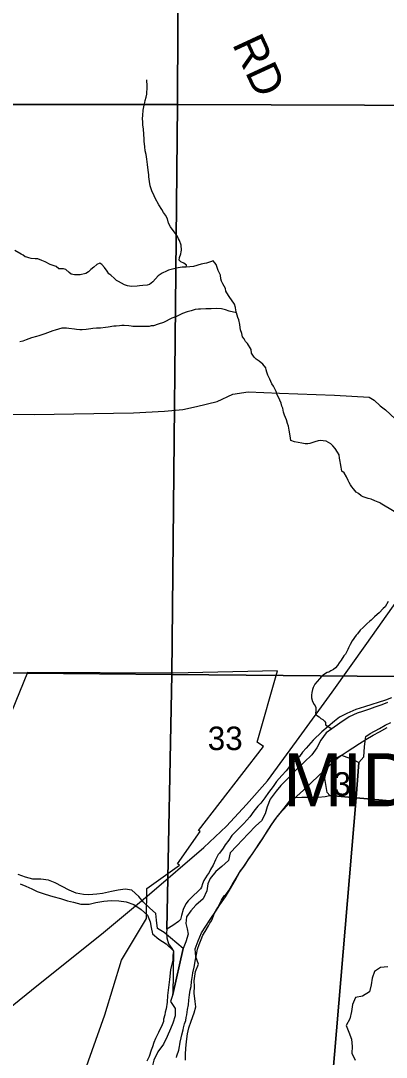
# Model space of a CAD drawing. Extents: x 0 to 34, y 0 to 22.
# Drawn here: x 3.881 to 4.533, y 15.439 to 17.286 of the extents above; entities that cross this region are included whole.
import ezdxf

# ---------------------------------------------------------------- set-up
doc = ezdxf.new("R2010")
doc.units = 0
for name, color, linetype in [('GM_X_Corporation', 7, 'Continuous'), ('GM_X_Corporation_Text', 7, 'Continuous'), ('GM_X_County_Road', 7, 'Continuous'), ('GM_X_Major_River', 7, 'Continuous'), ('GM_X_Minor_Lake', 7, 'Continuous'), ('GM_X_Minor_River', 7, 'Continuous'), ('GM_X_Rail_Line', 7, 'Continuous'), ('GM_X_Section_Text', 7, 'Continuous'), ('GM_X_Township_Road_Text', 7, 'Continuous')]:
    doc.layers.add(name, color=color, linetype=linetype)

msp = doc.modelspace()

# ---------------------------------------------------------------- linework, layer by layer
at = {"layer": 'GM_X_Corporation'}
for points in [[(4.1647, 18.1352), (4.1603, 17.1368), (3.1266, 17.137), (3.1398, 18.1413)], [(4.1647, 18.1352), (5.169, 18.1258), (5.1609, 17.1336), (4.1603, 17.1368)], [(4.1603, 17.1368), (4.1502, 16.1212), (3.1186, 16.1305), (3.1266, 17.137)], [(4.4839, 15.964), (4.4791, 15.9012), (4.4319, 15.9053), (4.4271, 15.9108), (4.423, 15.9356), (4.4289, 15.9641), (4.4529, 15.977), (4.4738, 15.9693)], [(4.4791, 15.9012), (5.4696, 15.8133), (5.3881, 14.7897), (4.6238, 14.8425), (4.6032, 14.8565), (4.5856, 14.8637), (4.5735, 14.8663), (4.5679, 14.8668), (4.5637, 14.865), (4.5556, 14.8606), (4.5464, 14.8574), (4.5354, 14.8542), (4.5274, 14.851), (4.4054, 15.0286)]]:
    msp.add_lwpolyline(points, close=True, dxfattribs=at)
for points in [[(4.6133, 16.1169), (4.1502, 16.1212), (4.1603, 17.1368), (5.1609, 17.1336)], [(3.1186, 16.1305), (4.1502, 16.1212), (4.1415, 15.6672), (4.1406, 15.66), (4.1412, 15.6517), (4.1447, 15.6406), (4.1506, 15.6325), (4.1532, 15.6279), (4.1523, 15.6204), (4.1521, 15.6117), (4.15, 15.6023), (4.1483, 15.5943), (4.1464, 15.577), (4.1424, 15.5486), (4.1418, 15.5369), (4.14, 15.5248), (4.1387, 15.5188), (4.1379, 15.5146), (4.1358, 15.5067), (4.1353, 15.5026), (4.1329, 15.4962), (4.1266, 15.4831), (4.1214, 15.4722), (4.1182, 15.4651), (4.1162, 15.4572), (4.1134, 15.4512), (4.1098, 15.4402), (4.1058, 15.432)], [(3.9341, 15.2418), (4.0311, 15.5141), (4.0604, 15.6115), (4.1055, 15.6858), (4.1057, 15.7394), (4.1642, 15.7809), (4.1606, 15.7834), (4.2008, 15.8408), (4.1977, 15.843), (4.3138, 15.9926), (4.3027, 16.0005), (4.3388, 16.1275), (4.1527, 16.1234), (3.8931, 16.1244), (3.7783, 15.844)], [(4.5417, 16.0791), (4.5314, 16.0751), (4.4936, 16.063), (4.4784, 16.0584), (4.4623, 16.0512), (4.4493, 16.0447), (4.4404, 16.038), (4.4176, 16.0185), (4.4022, 16.0036), (4.3897, 15.9895), (4.3832, 15.9825), (4.3777, 15.975), (4.3722, 15.9683), (4.3653, 15.9624), (4.3599, 15.9568), (4.354, 15.949), (4.3463, 15.9408), (4.337, 15.93), (4.3311, 15.9215), (4.3229, 15.9103), (4.3163, 15.901), (4.3089, 15.8916), (4.3034, 15.8861), (4.2968, 15.8771), (4.2894, 15.8674), (4.2789, 15.8552), (4.2638, 15.8407), (4.2576, 15.834), (4.2521, 15.8258), (4.2455, 15.8176), (4.242, 15.8116), (4.2354, 15.8027), (4.233, 15.8001), (4.2283, 15.7903), (4.2239, 15.7813), (4.2196, 15.7735), (4.2168, 15.7682), (4.2133, 15.763), (4.2074, 15.7537), (4.205, 15.7477), (4.203, 15.742), (4.2014, 15.7386), (4.1968, 15.7342), (4.1883, 15.7264), (4.1797, 15.7175), (4.1754, 15.7119), (4.1707, 15.7022), (4.1678, 15.6916), (4.1658, 15.6845), (4.1623, 15.6808), (4.1523, 15.6738), (4.1415, 15.6672), (4.1502, 16.1212), (4.6133, 16.1169)], [(5.4696, 15.8133), (4.4791, 15.9012), (4.4839, 15.964), (4.4928, 15.9744), (4.494, 15.9922), (4.4954, 16.0066), (4.4963, 16.0103), (4.5039, 16.0155), (4.5204, 16.0246), (4.5308, 16.0308), (4.5407, 16.0355)], [(4.159, 15.4384), (4.1594, 15.4411), (4.163, 15.4512), (4.1643, 15.4576), (4.1648, 15.4614), (4.1652, 15.4656), (4.1673, 15.4731), (4.1685, 15.4788), (4.1706, 15.4874), (4.1711, 15.4912), (4.1727, 15.498), (4.1751, 15.504), (4.176, 15.5097), (4.1769, 15.5146), (4.1786, 15.5236), (4.1799, 15.5323), (4.1809, 15.5406), (4.1818, 15.5501), (4.1831, 15.5584), (4.1848, 15.5651), (4.1857, 15.5735), (4.1875, 15.5844), (4.1879, 15.5889), (4.1901, 15.5991), (4.1926, 15.6131), (4.1943, 15.6221), (4.1961, 15.6312), (4.1989, 15.6395), (4.2025, 15.6485), (4.2057, 15.6564), (4.2096, 15.6631), (4.2155, 15.6728), (4.2183, 15.6777), (4.221, 15.6818), (4.2226, 15.6863), (4.2266, 15.6953), (4.2321, 15.7058), (4.2392, 15.7189), (4.2436, 15.7264), (4.2466, 15.729), (4.2494, 15.7323), (4.2517, 15.7357), (4.2592, 15.7484), (4.2651, 15.7581), (4.2729, 15.7712), (4.2776, 15.7772), (4.2808, 15.7824), (4.289, 15.794), (4.2929, 15.7992), (4.2976, 15.8067), (4.3081, 15.822), (4.312, 15.8283), (4.3187, 15.838), (4.325, 15.8485), (4.3281, 15.853), (4.3375, 15.8664), (4.346, 15.8768), (4.3569, 15.891), (4.3651, 15.9014), (4.3818, 15.9022), (4.411, 15.9023), (4.4235, 15.9032), (4.4319, 15.9053), (4.4791, 15.9012), (4.4054, 15.0286)]]:
    msp.add_lwpolyline(points, dxfattribs=at)
at = {"layer": 'GM_X_County_Road'}
msp.add_lwpolyline([(3.7241, 16.5854), (3.9049, 16.5844), (4.0823, 16.5872), (4.1373, 16.59), (4.1698, 16.5932), (4.1944, 16.5988), (4.2309, 16.6077), (4.2593, 16.6207), (4.2867, 16.6246), (4.3422, 16.6223), (4.4404, 16.619), (4.5023, 16.6152), (4.5112, 16.6097), (4.522, 16.6), (4.5311, 16.5928), (4.5572, 16.5681), (4.5938, 16.5369), (4.6091, 16.5261)], dxfattribs=at)
at = {"layer": 'GM_X_Major_River'}
msp.add_line((4.1705, 15.6327), (4.1523, 15.5504), dxfattribs=at)
for points in [[(4.535, 16.0708), (4.5246, 16.0669), (4.5124, 16.0627), (4.5028, 16.0592), (4.4905, 16.0549), (4.4805, 16.0518), (4.4667, 16.0457), (4.4497, 16.034), (4.4357, 16.0241), (4.4257, 16.0172), (4.4162, 16.0038), (4.409, 15.9903), (4.3999, 15.9777), (4.3862, 15.9644), (4.3734, 15.9522), (4.3593, 15.9381), (4.3448, 15.9233), (4.3362, 15.9129), (4.3256, 15.8988), (4.3206, 15.8853), (4.3169, 15.8728), (4.3101, 15.8601), (4.2999, 15.8509), (4.2863, 15.8372), (4.2761, 15.8265), (4.2663, 15.8153), (4.2542, 15.8031), (4.2512, 15.7896), (4.2395, 15.7789), (4.229, 15.7697), (4.2187, 15.7574), (4.2143, 15.7477), (4.2128, 15.7355), (4.206, 15.7213), (4.1931, 15.7099), (4.1841, 15.6999), (4.1766, 15.6891), (4.1755, 15.6769), (4.1779, 15.6674), (4.1795, 15.6579), (4.1754, 15.6443), (4.1705, 15.6327)], [(4.193, 15.5284), (4.1918, 15.538), (4.1903, 15.5532), (4.191, 15.5657), (4.1902, 15.5752), (4.1925, 15.5915), (4.1978, 15.6046), (4.1929, 15.6176), (4.1917, 15.6317), (4.1974, 15.646), (4.2035, 15.6606), (4.2107, 15.6722), (4.2186, 15.6845), (4.2301, 15.7009), (4.2361, 15.7106), (4.2459, 15.7248), (4.2531, 15.7364), (4.2631, 15.7536), (4.2707, 15.7678), (4.2797, 15.7797), (4.2861, 15.7894), (4.2964, 15.8047), (4.3055, 15.8177), (4.3126, 15.8289), (4.321, 15.8424), (4.3289, 15.8543), (4.336, 15.8643), (4.3462, 15.8774), (4.3583, 15.8896), (4.3732, 15.9043), (4.3849, 15.915), (4.4118, 15.9405), (4.4277, 15.9553), (4.4406, 15.9674), (4.4507, 15.9755), (4.4627, 15.9839), (4.4728, 15.9905), (4.4851, 15.9978), (4.496, 16.0051), (4.5095, 16.0127), (4.5203, 16.0188), (4.5341, 16.0264)], [(4.1523, 15.5504), (4.1481, 15.538), (4.1565, 15.5256), (4.1565, 15.5127), (4.152, 15.4992), (4.1483, 15.4894), (4.1422, 15.4755), (4.1354, 15.462), (4.1255, 15.4482), (4.1183, 15.4333), (4.1145, 15.4193), (4.1127, 15.4091), (4.1103, 15.3928), (4.1077, 15.3815), (4.1052, 15.371), (4.1015, 15.3604), (4.095, 15.3477), (4.0871, 15.3361), (4.0742, 15.3228)], [(4.1745, 15.4333), (4.1748, 15.4443), (4.1754, 15.4541), (4.1765, 15.467), (4.1784, 15.4802), (4.1806, 15.4912), (4.1847, 15.5028), (4.1901, 15.5179), (4.193, 15.5284)]]:
    msp.add_lwpolyline(points, dxfattribs=at)
at = {"layer": 'GM_X_Minor_Lake'}
msp.add_lwpolyline([(4.5356, 15.5997), (4.5223, 15.5985), (4.5115, 15.5916), (4.5077, 15.5796), (4.5059, 15.5675), (4.5025, 15.5554), (4.4905, 15.5478), (4.4775, 15.5451), (4.4723, 15.5327), (4.4704, 15.5202), (4.4674, 15.507), (4.4614, 15.4954), (4.4656, 15.4832), (4.4709, 15.4709), (4.4721, 15.4579), (4.4714, 15.4458), (4.4771, 15.4335)], dxfattribs=at)
at = {"layer": 'GM_X_Minor_River'}
msp.add_line((4.1523, 15.5504), (4.1705, 15.6327), dxfattribs=at)
for points in [[(4.1757, 16.8471), (4.1765, 16.8505), (4.1716, 16.8539), (4.1663, 16.8562), (4.1637, 16.8597), (4.1641, 16.8639), (4.1664, 16.8707), (4.1672, 16.8741), (4.1676, 16.8775), (4.1673, 16.8862), (4.1643, 16.8942), (4.1625, 16.8976), (4.1598, 16.903), (4.1546, 16.9102), (4.1482, 16.919), (4.1445, 16.9255), (4.1427, 16.9331), (4.1393, 16.9395), (4.1356, 16.9441), (4.1326, 16.9498), (4.127, 16.9582), (4.1206, 16.9697), (4.1188, 16.9739), (4.1147, 16.983), (4.1117, 16.9921), (4.1103, 16.9997), (4.1092, 17.0081), (4.1092, 17.0115), (4.1081, 17.0199), (4.1071, 17.0297), (4.106, 17.0396), (4.1046, 17.0476), (4.1031, 17.0544), (4.102, 17.0616), (4.1013, 17.0715), (4.101, 17.0749), (4.1007, 17.084), (4.1, 17.0931), (4.0989, 17.1007), (4.0985, 17.1056), (4.0982, 17.1121), (4.0986, 17.1174), (4.0995, 17.1269), (4.101, 17.1356), (4.1022, 17.1405), (4.103, 17.1439), (4.1049, 17.15), (4.1057, 17.1553), (4.1058, 17.1594), (4.1065, 17.1644), (4.1066, 17.1727), (4.1059, 17.1776), (4.1059, 17.181)], [(4.1409, 16.8398), (4.1333, 16.8361), (4.126, 16.8312), (4.1215, 16.8263), (4.1165, 16.8207), (4.1108, 16.8162), (4.1066, 16.8151), (4.0987, 16.814), (4.093, 16.8137), (4.0885, 16.813), (4.0786, 16.8127), (4.0711, 16.8135), (4.0658, 16.8155), (4.0556, 16.8212), (4.0519, 16.8232), (4.0485, 16.8266), (4.0417, 16.8327), (4.0379, 16.8351), (4.0353, 16.8396), (4.0305, 16.8465), (4.0256, 16.8515), (4.0218, 16.8538), (4.0165, 16.8519), (4.0112, 16.8471), (4.0062, 16.8429), (4.0017, 16.8388), (3.9971, 16.8358), (3.9873, 16.8332), (3.977, 16.8333), (3.971, 16.8345), (3.9676, 16.8372), (3.9616, 16.843), (3.9571, 16.8441), (3.9529, 16.8442), (3.9488, 16.8438), (3.9443, 16.8481), (3.9333, 16.8519), (3.9247, 16.8562), (3.9186, 16.8589), (3.9115, 16.862), (3.9069, 16.8617), (3.8994, 16.8625), (3.8956, 16.8633), (3.8922, 16.8645), (3.8888, 16.8653), (3.8854, 16.8683), (3.8816, 16.8702), (3.8707, 16.8768)], [(4.5217, 16.4271), (4.5183, 16.4283), (4.5123, 16.4302), (4.5055, 16.4333), (4.5002, 16.4349), (4.4949, 16.4361), (4.4915, 16.4376), (4.4881, 16.4395), (4.4829, 16.4434), (4.4787, 16.4461), (4.4742, 16.4518), (4.4712, 16.4552), (4.4686, 16.4587), (4.4664, 16.4632), (4.4645, 16.4667), (4.4615, 16.4735), (4.4574, 16.4804), (4.4536, 16.4831), (4.4522, 16.4903), (4.4511, 16.4971), (4.4504, 16.5006), (4.4493, 16.5066), (4.4486, 16.5123), (4.4456, 16.5173), (4.4418, 16.5238), (4.4373, 16.5287), (4.4336, 16.5318), (4.4253, 16.5368), (4.4147, 16.5381), (4.4113, 16.5373), (4.4052, 16.5355), (4.3965, 16.5325), (4.3927, 16.5318), (4.3882, 16.5322), (4.3822, 16.533), (4.3693, 16.5354), (4.3625, 16.5378), (4.3614, 16.5461), (4.3593, 16.5564), (4.3586, 16.5636), (4.3567, 16.5682), (4.3549, 16.575), (4.3511, 16.5834), (4.3497, 16.5887), (4.3482, 16.5956), (4.3467, 16.599), (4.3452, 16.6047), (4.3408, 16.615), (4.3382, 16.6192), (4.3363, 16.6252), (4.3315, 16.6348), (4.3289, 16.639), (4.3248, 16.6473), (4.3214, 16.6546), (4.3199, 16.6599), (4.3184, 16.6637), (4.3181, 16.6675), (4.3125, 16.674), (4.3061, 16.6794), (4.3008, 16.6832), (4.2971, 16.6863), (4.2926, 16.6939), (4.2915, 16.7), (4.2851, 16.711), (4.2818, 16.7145), (4.2795, 16.7191), (4.2765, 16.7229), (4.275, 16.7286), (4.2728, 16.7354), (4.2721, 16.7396), (4.2714, 16.7445), (4.2696, 16.7533), (4.2681, 16.7575), (4.2655, 16.7655), (4.2644, 16.7704), (4.264, 16.7749), (4.2618, 16.7807), (4.257, 16.7887), (4.254, 16.7929), (4.2513, 16.7967), (4.2465, 16.8039), (4.2458, 16.8089), (4.2413, 16.8173), (4.239, 16.8218), (4.2379, 16.8264), (4.2369, 16.8325), (4.2331, 16.8412), (4.2294, 16.8515), (4.2272, 16.8549), (4.2238, 16.858), (4.2193, 16.8565), (4.2124, 16.8543), (4.2086, 16.8536), (4.2026, 16.8521), (4.1893, 16.8484), (4.1757, 16.8471), (4.1689, 16.8467), (4.1583, 16.8453), (4.1537, 16.8442), (4.1446, 16.8413), (4.1409, 16.8398)], [(4.2655, 16.7655), (4.2523, 16.7686), (4.2459, 16.7709), (4.2387, 16.7729), (4.2296, 16.773), (4.2205, 16.7727), (4.2171, 16.7727), (4.2107, 16.7724), (4.2016, 16.7721), (4.1978, 16.7721), (4.1922, 16.7714), (4.185, 16.7692), (4.1778, 16.7674), (4.1694, 16.7641), (4.1588, 16.7592), (4.1504, 16.7559), (4.1353, 16.7485), (4.1262, 16.7451), (4.1178, 16.7425), (4.1137, 16.7422), (4.1099, 16.7411), (4.1034, 16.7412), (4.0947, 16.7409), (4.091, 16.7409), (4.0853, 16.7413), (4.0811, 16.7414), (4.0777, 16.7418), (4.0736, 16.7422), (4.0653, 16.7427), (4.0611, 16.7427), (4.0573, 16.7423), (4.0509, 16.742), (4.0471, 16.7417), (4.0369, 16.7399), (4.0323, 16.7392), (4.0232, 16.7385), (4.0161, 16.7382), (4.0096, 16.7379), (4.0062, 16.7371), (3.9975, 16.7361), (3.9903, 16.7354), (3.9862, 16.7354), (3.9805, 16.7358), (3.9767, 16.7363), (3.9669, 16.7379), (3.9627, 16.7383), (3.9544, 16.7384), (3.9427, 16.7347), (3.9385, 16.7332), (3.9286, 16.7299), (3.9241, 16.7284), (3.9131, 16.7247), (3.9089, 16.7236), (3.9002, 16.7207), (3.8907, 16.7177), (3.8847, 16.7151), (3.8794, 16.7136)], [(4.5217, 16.4271), (4.5469, 16.412)], [(4.5361, 16.2511), (4.5306, 16.2418), (4.5272, 16.2384), (4.5198, 16.2306), (4.5163, 16.228), (4.5117, 16.2239), (4.5059, 16.2179), (4.5032, 16.2157), (4.4981, 16.2113), (4.4912, 16.2049), (4.4858, 16.2001), (4.4811, 16.1934), (4.4788, 16.1908), (4.4721, 16.181), (4.4682, 16.1746), (4.4654, 16.1686), (4.4638, 16.1656), (4.4599, 16.1573), (4.4572, 16.1543), (4.4521, 16.1465), (4.4489, 16.1416), (4.4454, 16.1371), (4.4419, 16.133), (4.4385, 16.13), (4.4338, 16.1275), (4.43, 16.1249), (4.4273, 16.1242), (4.4223, 16.1216), (4.4173, 16.1175), (4.4138, 16.1134), (4.4092, 16.1082), (4.4053, 16.1037), (4.4021, 16.0977), (4.4009, 16.0939), (4.3997, 16.0886), (4.3992, 16.0841), (4.3995, 16.0791), (4.4009, 16.073), (4.4038, 16.0677), (4.406, 16.0649), (4.4071, 16.0619), (4.407, 16.0558), (4.4062, 16.0524), (4.4069, 16.0497), (4.4103, 16.0474), (4.4129, 16.0454), (4.4162, 16.0427), (4.4196, 16.0407), (4.4226, 16.038), (4.4241, 16.0353), (4.4244, 16.0311), (4.4357, 16.0241)], [(4.1705, 15.6327), (4.1367, 15.6613), (4.1248, 15.6684), (4.1233, 15.6833), (4.1217, 15.6947), (4.1106, 15.7049), (4.0991, 15.7158), (4.0918, 15.7255), (4.0792, 15.7365), (4.0675, 15.7383), (4.0549, 15.7367), (4.0427, 15.734), (4.0266, 15.7307), (4.0167, 15.7294), (4.0026, 15.7283), (3.9931, 15.7285), (3.9799, 15.7312), (3.9672, 15.7368), (3.9548, 15.7428), (3.9425, 15.7496), (3.9304, 15.7541), (3.9168, 15.756), (3.9024, 15.7564), (3.8896, 15.7594), (3.8764, 15.7647)], [(3.8801, 15.7479), (3.8899, 15.7438), (3.9008, 15.7386), (3.9105, 15.7342), (3.9244, 15.7296), (3.9384, 15.7254), (3.9519, 15.7217), (3.9644, 15.7175), (3.9749, 15.715), (3.9881, 15.7116), (4.0029, 15.7116), (4.0152, 15.7143), (4.0289, 15.7169), (4.0422, 15.7181), (4.0559, 15.7174), (4.0691, 15.7155), (4.0827, 15.7109), (4.0957, 15.7019), (4.1072, 15.6921), (4.1118, 15.6798), (4.1134, 15.6699), (4.1158, 15.6588), (4.1273, 15.6494)], [(4.1273, 15.6494), (4.1403, 15.6407), (4.1533, 15.6286)], [(4.1533, 15.6286), (4.1523, 15.5504)]]:
    msp.add_lwpolyline(points, dxfattribs=at)
at = {"layer": 'GM_X_Rail_Line'}
msp.add_lwpolyline([(3.8337, 15.5051), (3.9125, 15.5684), (4.025, 15.6578), (4.1108, 15.7292), (4.2077, 15.8126), (4.2476, 15.8508), (4.2837, 15.8891), (4.3211, 15.9313), (4.3725, 16.0019), (4.4359, 16.0894), (4.4979, 16.1764), (4.5524, 16.2535), (4.6645, 16.4136), (4.7287, 16.5084), (4.8593, 16.6913), (4.9773, 16.8591), (5.0754, 16.9979), (5.1824, 17.1481), (5.2189, 17.2021), (5.2481, 17.2571), (5.2725, 17.3103)], dxfattribs=at)

# ---------------------------------------------------------------- texts
at = {"layer": 'GM_X_Corporation_Text'}
msp.add_text('MIDDLETOWN', height=0.0947, rotation=0, dxfattribs=at).set_placement((4.3488, 15.886))
at = {"layer": 'GM_X_Section_Text'}
for s, height, p in [('33', 0.04186, (4.2144, 15.9862)), ('3', 0.0419, (4.4385, 15.9049))]:
    msp.add_text(s, height=height, rotation=0, dxfattribs=at).set_placement(p)
at = {"layer": 'GM_X_Township_Road_Text'}
msp.add_text('RD', height=0.05682, rotation=294.8105, dxfattribs=at).set_placement((4.2573, 17.2447))

doc.saveas('drawing.dxf')
